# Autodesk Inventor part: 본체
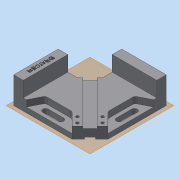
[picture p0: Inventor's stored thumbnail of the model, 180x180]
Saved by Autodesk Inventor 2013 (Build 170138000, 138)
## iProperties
Created: 2019-04
Part Number: 본체
Material: 일반
Document SubType Name: Modeling
Designer: dgall
Density: 1 g/cm^3
Author: dgall
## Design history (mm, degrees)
sketch "스케치2"
  geometry: L1 (-60, 60)-(60, 60); L2 (60, 60)-(60, -60); L3 (60, -60)-(-60, -60); L4 (-60, -60)-(-60, 60); 3 further points
  constraints: 8 end point, 2 midpoint, 2 parallel, 1 horizontal, 1 horizontal alignment, 1 perpendicular, 1 vertical alignment
  dimensions: "d3" = 120 distance of L1.start L1.end; "d5" = 120 distance of L1.end L2.end
extrude "돌출1" new body sketch "스케치2" distance "d6" = 42; taper "d7" = 0 deg
sketch "스케치3"
  geometry: L1 (60, 60)-(-60, 60) reference; L2 (-60, 60)-(-60, -60) reference; L3 (-60, -60)-(60, -60) reference; L4 (-45, 45)-(63.533, 45); L5 (63.533, 45)-(63.533, -84.63); L6 (63.533, -84.63)-(-45, -84.63); L7 (-45, -84.63)-(-45, 45); 1 further point
  constraints: 8 end point, 2 parallel, 2 perpendicular
  dimensions: "d8" = 15 distance between parallel lines of L7 L2; "d9" = 15 distance between parallel lines of L1 L4
extrude "돌출2" cut sketch "스케치3" distance "d10" = 24; taper "d11" = 0 deg
sketch "스케치4"
  geometry: L1 (60, -60)-(31.716, -60); L2 (60, -60)-(-60, -60) reference; L3 (31.716, -60)-(60, -31.716); L4 (60, 60)-(60, -60) reference; L5 (60, -60)-(60, -31.716); L6 (60, -60)-(45.858, -45.858); 1 further point
  constraints: 8 end point, 2 point on line, 1 collinear, 1 midpoint, 1 perpendicular
  dimensions: "d12" = 45 deg angle of L1 L6; "d13" = 20 distance of L1.start L6.end
extrude "돌출3" cut sketch "스케치4" distance "d14" = 24; taper "d15" = 0 deg
sketch "스케치5"
  geometry: L1 (31.716, -60)-(60, -31.716) reference; L2 (-45, -60)-(-45, 45) reference; L3 (45.858, -45.858)-(-45, 45); L4 (51.515, -40.201)-(-48.686, 60); L5 (60, 60)-(-60, 60) reference; L6 (40.201, -51.515)-(-60, 48.686); L7 (-60, -60)-(-60, 60) reference; L8 (-60, 48.686)-(-48.686, 60); L9 (40.201, -51.515)-(51.515, -40.201); L10 (60, -31.716)-(31.716, -60) reference; L11 (51.515, -40.201)-(40.201, -51.515); 1 further point
  constraints: 12 end point, 6 point on line, 2 collinear, 2 perpendicular, 2 symmetric about line, 1 midpoint, 1 parallel
  dimensions: "d16" = 8 distance between parallel lines of L3 L4
extrude "돌출4" cut sketch "스케치5" distance "d18" = 3.5; taper "d19" = 0 deg
sketch "스케치6"
  geometry: L1 (51.515, -40.201)-(40.201, -51.515) reference; L2 (45.858, -45.858)-(-19.903, 19.903); L3 (-60, 60)-(-10, 60); L4 (-10, 60)-(-10, 10); L5 (-10, 10)-(-60, 10); L6 (-60, 10)-(-60, 60); L7 (-19.903, 19.903)-(-10, 29.806); L8 (-19.903, 19.903)-(-29.806, 10); 1 further point
  constraints: 14 end point, 3 equal length, 3 perpendicular, 3 point on line, 1 horizontal, 1 midpoint
  dimensions: "d22" = 93 distance of L2.start L2.end; "d23" = 50 distance of L3.start L3.end
extrude "돌출5" cut sketch "스케치6" stored distance "d24" = 3.5; taper "d25" = 0 deg
sketch "스케치7"
  geometry: L1 (31.716, -60)-(-45, -60) reference; L2 (40.201, -51.515)-(-25.56, 14.246) reference; L3 (-40, -60)-(-30, -40); L4 (-30, -40)-(11.716, -40); L5 (11.716, -40)-(31.716, -60); L6 (-60, 10)-(-60, -60) reference; L7 (51.515, -40.201)-(40.201, -51.515) reference; L8 (45.858, -45.858)-(26.857, -26.857); L9 (45.858, -45.858)-(31.716, -60); L10 (31.716, -60)-(-40, -60); L11 (40, 30)-(40, -11.716); L12 (60, 40)-(40, 30); L13 (60, -31.716)-(60, 45); L14 (40, -11.716)-(60, -31.716); 1 further point
  constraints: 20 end point, 5 symmetric about line, 4 point on line, 2 parallel, 2 perpendicular, 1 midpoint
  dimensions: "d26" = 20 distance from line of L6 L3.start; "d27" = 20 distance between parallel lines of L1 L4; "d28" = 30 distance from line of L6 L3.end; "d29" = 20 distance of L8.start L5.end
extrude "돌출6" cut sketch "스케치7" distance "d30" = 10; taper "d31" = 0 deg
extrude "돌출7" cut sketch "스케치7" distance "d32" = 10; taper "d33" = 0 deg
sketch "스케치8"
  geometry: L1 (-12, 18)-(28, 18) reference; L2 (14, 15)-(2, 15); L3 (2, 15)-(2, 18); L4 (2, 18)-(14, 18); L5 (14, 18)-(14, 15); 2 further points
  constraints: 8 end point, 2 midpoint, 2 parallel, 1 horizontal, 1 perpendicular, 1 point on line
  dimensions: "d34" = 12 distance of L2.start L2.end; "d36" = 3 distance of L4.end L2.start
extrude "돌출8" cut sketch "스케치8" stored distance "d37" = 0; taper "d38" = 0 deg
sketch "스케치9" dims "d39" = 9
  geometry: L1 (31.716, -60)-(-40, -60) reference; L2 (-60, 10)-(-60, -60) reference; L3 (-20, -45.5)-(4, -45.5); L4 (4, -45.5)-(4, -54.5); L5 (4, -54.5)-(-20, -54.5); L6 (-20, -54.5)-(-20, -45.5); L7 (41.615, -50.101)-(50.101, -41.615) reference; L8 (45.858, -45.858)-(-19.253, 19.253); L9 (41.615, -50.101)-(-24.146, 15.66) reference; L10 (45.5, 20)-(45.5, -4); L11 (54.5, -4)-(54.5, 20); L12 (54.5, 20)-(45.5, 20); L13 (45.5, -4)-(54.5, -4); C1 r 4.5 at (4, -50); C2 r 4.5 at (50, -4); 4 further points
  constraints: 18 end point, 6 symmetric about line, 3 midpoint, 3 parallel, 2 centre point, 2 horizontal, 1 coincident, 1 horizontal alignment, 1 perpendicular, 1 vertical alignment, 6 other
  dimensions: "d41" = 40 distance from line of L2 point (-20, -50); "d42" = 10 distance from line of L1 point (-20, -50); "d43" = 24 distance of L3.start L3.end; "d44" = 9 diameter of C1
extrude "돌출9" cut sketch "스케치9" stored distance "d45" = 10; taper "d46" = 0 deg
extrude "돌출10" cut sketch "스케치9" stored distance "d47" = 10; taper "d48" = 0 deg
sketch "스케치10"
  geometry: L1 (11.716, -40)-(31.716, -60) reference; L2 (41.615, -50.101)-(50.101, -41.615) reference; L3 (45.858, -45.858)-(-19.903, 19.903); L4 (-15.66, 24.146)-(-24.146, 15.66) reference; L5 (41.615, -41.615)-(31.716, -51.515); L6 (31.716, -51.515)-(-25.241, 5.442); L7 (23.23, -43.029)-(33.13, -33.13); 5 further points
  constraints: 8 end point, 3 perpendicular, 3 point on line, 2 coincident, 2 midpoint, 2 symmetric about line
  dimensions: "d50" = 6 distance between parallel lines of L2 L5; "d51" = 14 distance between parallel lines of L3 L6; "d52" = 12 distance between parallel lines of L5 L7
hole "구멍1" sketch "스케치10" diameter "d53" = 4.5; stored, may be unused: countersink angle "d57" = 90 deg, drill point angle "d59" = 118 deg; dims "d54" = 6, "d55" = 4, "d56" = 2, "d58" = 8
hole "구멍2" sketch "스케치10" diameter "d60" = 4.5; stored, may be unused: countersink angle "d64" = 90 deg, drill point angle "d66" = 118 deg; dims "d61" = 6, "d62" = 4, "d63" = 2, "d65" = 8
sketch "스케치11"
  geometry: C1 r 2.25 at (-31.716, -51.515) reference; C2 r 2.25 at (-23.23, -43.029) reference; C3 r 2.25 at (-43.029, -23.23) reference; C4 r 2.25 at (-51.515, -31.716) reference; 5 further points
  constraints: 4 coincident
hole "구멍3" sketch "스케치11" diameter "d67" = 8; stored, may be unused: countersink angle "d71" = 90 deg, drill point angle "d73" = 0 deg; dims "d68" = 6, "d69" = 4, "d70" = 2, "d72" = 10
hole "구멍4" sketch "스케치11" diameter "d74" = 8; stored, may be unused: countersink angle "d78" = 90 deg, drill point angle "d80" = 0 deg; dims "d75" = 6, "d76" = 4, "d77" = 2, "d79" = 10
sketch "스케치12"
  geometry: L1 (-45, 10)-(-60, 10) reference; 2 further points
  constraints: 1 other
  dimensions: "d81" = 7.5 horizontal distance of point (-52.5, -25) L1.end; "d82" = 35 distance from line of L1 point (-52.5, -25)
feature "엠보싱1" sketch "스케치12" dims "d3" = 120, "d5" = 120, "d83" = 0.5, "d84" = 0
fillet "모깎기1" dims "d85" = 5
node "솔리드1"
